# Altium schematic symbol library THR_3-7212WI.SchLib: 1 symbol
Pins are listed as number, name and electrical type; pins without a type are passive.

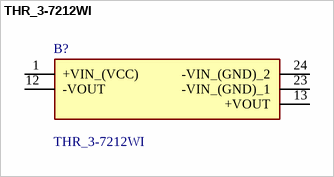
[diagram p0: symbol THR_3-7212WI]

## THR_3-7212WI
designator B?
3 Watt DC/DC converter, industrial, 4:1 input, reinforced isolation (3000 VAC), encapsulated, DIP-24; Manufacturer_Name: Traco Power; Manufacturer_Part_Number: THR 3-7212WI; Geometry.Height: 12.5mm
footprint THR37212WI
pins: 1 +VIN_(VCC), 12 -VOUT, 13 +VOUT, 23 -VIN_(GND)_1, 24 -VIN_(GND)_2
